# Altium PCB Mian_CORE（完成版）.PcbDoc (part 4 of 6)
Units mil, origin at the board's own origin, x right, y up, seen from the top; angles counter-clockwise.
Board outline 2755.91 x 1771.65 mil, 4 copper layers (TOP, GND02, PWR03, BOTTOM); 61 components, 130 nets, 4907 pads, 497 vias.
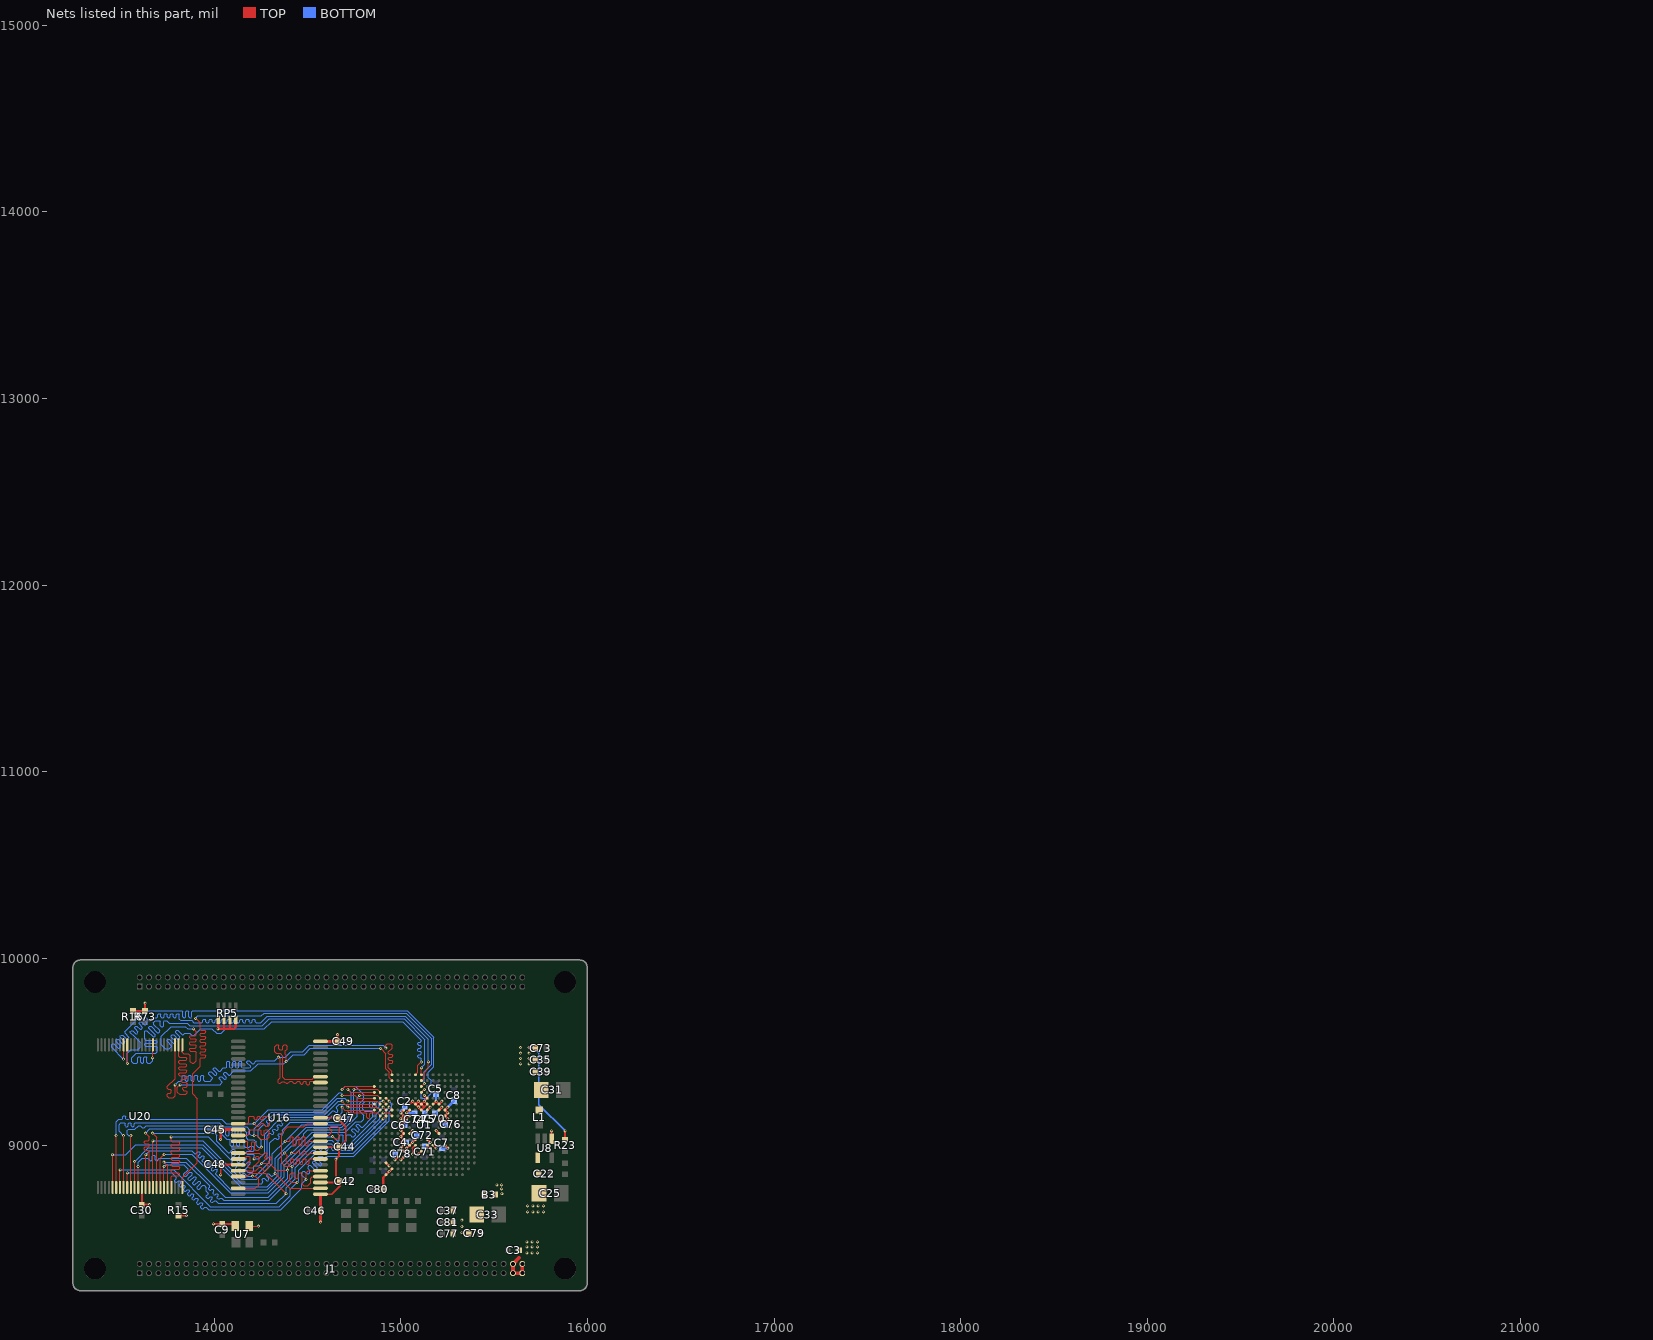
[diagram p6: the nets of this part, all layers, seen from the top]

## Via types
v1: diameter 16, hole 8, TOP to BOTTOM, tented both sides, 497 vias

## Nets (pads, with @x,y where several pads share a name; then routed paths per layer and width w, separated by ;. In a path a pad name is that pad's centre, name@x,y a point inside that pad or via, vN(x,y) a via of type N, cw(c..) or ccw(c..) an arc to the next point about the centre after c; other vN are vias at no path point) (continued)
A13: U1.R1 U16.20 U20.3 | length 2952.1
  TOP w5.5: v1(13790,9323) 13790.01,9264.01 13780,9254 13756,9254 13749,9261 13749,9272 13755,9278 13764,9278 13769,9283 13769,9294 13765,9298 13755,9298 13749,9304 13749,9314 13790.01,9355.01 U20.3@13790.01,9536.89 ; v1(14344,9471) 14353,9462 14353,9360 14344,9351 14344,9334 14348,9330 14354,9330 14364,9340 14376,9340 14386,9330 14395,9330 14407,9342 14415,9342 14425,9332 14437,9332 14447,9342 14456.3,9342 14461.25,9337.05 14461.25,9330.37 14466.2,9325.42 14472.8,9325.42 14477.75,9330.37 14477.75,9337.05 14482.7,9342 14489.3,9342 14494.25,9337.05 14494.25,9328.95 14499.2,9324 14505.8,9324 14510.75,9328.95 14510.75,9337.05 14515.7,9342 14530,9342 14539,9333 14567.5,9333 U16.20@14569.47,9334.98 ; v1(14920,9519) 14920,9536 14928,9544 14947,9544 14955,9536 14955,9520 14934,9499 14934,9491.7 14938.95,9486.75 14951.05,9486.75 14956,9481.8 14956,9475.2 14951.05,9470.25 14938.95,9470.25 14934,9465.3 14934,9458.7 14938.95,9453.75 14951.05,9453.75 14956,9448.8 14956,9442.2 14951.05,9437.25 14938.95,9437.25 14934,9432.3 14934,9413.77 14952.77,9395 U1.R1@14952.77,9376.72
  BOTTOM w5.5: v1(13790,9323) 13810,9343 13823.3,9343 13828.25,9347.95 13828.25,9369.05 13833.2,9374 13839.8,9374 13844.75,9369.05 13844.75,9347.95 13849.7,9343 13856.3,9343 13861.25,9347.95 13861.25,9369.05 13866.2,9374 13872.8,9374 13877.75,9369.05 13877.75,9347.95 13882.7,9343 13889.3,9343 13894.25,9347.95 13894.25,9369.05 13899.2,9374 13905.8,9374 13910.75,9369.05 13910.75,9347.95 13915.7,9343 13922.3,9343 13927.25,9347.95 13927.25,9369.05 13932.2,9374 13938.8,9374 13943.75,9369.05 13943.75,9347.95 13948.7,9343 13979,9343 13990.31,9354.31 13990.31,9361.31 13971.86,9379.77 13971.86,9386.77 13976.52,9391.43 13983.52,9391.43 14001.98,9372.98 14008.98,9372.98 14013.65,9377.65 14013.65,9384.65 13995.19,9403.1 13995.19,9410.1 13999.86,9414.77 14006.86,9414.77 14025.31,9396.31 14032.31,9396.31 14049,9413 14061.3,9413 14066.25,9417.95 14066.25,9444.05 14071.2,9449 14077.8,9449 14082.75,9444.05 14082.75,9417.95 14087.7,9413 14094.3,9413 14099.25,9417.95 14099.25,9444.05 14104.2,9449 14110.8,9449 14115.75,9444.05 14115.75,9417.95 14120.7,9413 14127.3,9413 14132.25,9417.95 14132.25,9444.05 14137.2,9449 14143.8,9449 14148.75,9444.05 14148.75,9417.95 14153.7,9413 14188,9413 14192,9417 14192,9424 14175.67,9440.33 14175.67,9447.33 14180.33,9452 14187.33,9452 14203.67,9435.67 14210.67,9435.67 14226,9451 14324,9451 v1(14344,9471) 14381,9471 14410,9500 14475,9500 14509,9534 14905,9534 v1(14920,9519)
A14: U1.R2 U16.21 U20.2 | length 2777.8
  TOP w5.5: U20.2@13809.69,9536.89 13809.69,9474.7 13814.64,9469.75 13848.74,9469.75 13853.69,9464.8 13853.69,9458.2 13848.74,9453.25 13814.64,9453.25 13809.69,9448.3 13809.69,9441.7 13814.64,9436.75 13848.74,9436.75 13853.69,9431.8 13853.69,9425.2 13848.74,9420.25 13814.64,9420.25 13809.69,9415.3 13809.69,9408.7 13814.64,9403.75 13848.74,9403.75 13853.69,9398.8 13853.69,9392.2 13848.74,9387.25 13814.64,9387.25 13809.69,9382.3 13809.69,9375.7 13814.64,9370.75 13848.74,9370.75 13853.69,9365.8 13853.69,9358.7 13848.74,9353.75 13828.64,9353.75 13823.69,9348.8 13823.69,9342.2 13828.64,9337.25 13846.75,9337.25 13856,9328 13856,9316 13851,9311 13836,9311 13831,9306 13831,9298 13837,9292 13851,9292 13856,9287 13856,9280 13847.5,9271.5 13814.5,9271.5 13803,9283 13803,9309 v1(13817,9323) ; v1(14385.45,9447.46) 14385.45,9483.55 14382,9487 14382,9504 14392,9514 14392,9529 14384,9537 14375,9537 14368,9530 14368,9513 14365,9510 14352,9510 14347,9515 14347,9532 14342,9537 14335,9537 14324,9526 14324,9500 14332,9492 14353,9492 14368,9477 14368,9364 14379,9353 14526,9353 14539.47,9366.47 U16.21@14569.47,9366.47 ; v1(14892,9518.45) 14920,9490.45 14920,9408.02 14937.02,9391 14937.02,9360.97 U1.R2@14952.77,9345.22
  BOTTOM w5.5: v1(13817,9323) 14032,9323 14041.76,9332.76 14041.76,9339.76 14027.54,9353.97 14027.54,9360.97 14032.21,9365.64 14039.21,9365.64 14053.42,9351.42 14060.42,9351.42 14065.09,9356.09 14065.09,9363.09 14050.88,9377.3 14050.88,9384.3 14055.54,9388.97 14062.54,9388.97 14076.76,9374.76 14083.76,9374.76 14106,9397 14197,9397 14236,9436 14373.98,9436 v1(14385.45,9447.46) 14422.98,9485 14482,9485 14515.45,9518.45 v1(14892,9518.45)
A15: U1.L1 U20.1 | length 2803.5
  TOP w5.5: U20.1@13829.38,9536.89 13829.38,9497.62 13837,9490 13862,9490 13873,9479 13873,9446 13882,9437 13890,9437 13904,9451 13904,9498.3 13899.05,9503.25 13872.95,9503.25 13868,9508.2 13868,9514.8 13872.95,9519.75 13899.05,9519.75 13904,9524.7 13904,9531.3 13899.05,9536.25 13872.95,9536.25 13868,9541.2 13868,9547.8 13872.95,9552.75 13899.05,9552.75 13904,9557.7 13904,9564.3 13899.05,9569.25 13872.95,9569.25 13868,9574.2 13868,9580.8 13872.95,9585.75 13899.05,9585.75 13904,9590.7 13904,9608 v1(13889,9623) ; U1.L1@15078.76,9376.72 15092,9389.96 15092,9427 v1(15110,9445)
  BOTTOM w5.5: v1(13889,9623) 13857,9623 13845,9635 13769,9635 13716,9582 13716,9537 13738,9515 13759,9515 13769.86,9525.86 13769.86,9532.86 13747.16,9555.56 13747.16,9562.56 13751.83,9567.23 13758.83,9567.23 13781.53,9544.53 13788.53,9544.53 13793.19,9549.19 13793.19,9556.2 13770.5,9578.89 13770.5,9585.89 13775.16,9590.56 13782.16,9590.56 13804.86,9567.86 13811.86,9567.86 13816.53,9572.53 13816.53,9579.53 13793.83,9602.23 13793.83,9609.23 13798.5,9613.9 13805.5,9613.9 13828.2,9591.2 13835.2,9591.2 13843,9599 13870,9599 13880,9589 13894,9589 13928,9623 13988,9623 14013,9598 14039,9598 14063,9622 14269,9622 14309,9662 15010,9662 15110,9562 15110,9555.7 15105.05,9550.75 15094.95,9550.75 15090,9545.8 15090,9539.2 15094.95,9534.25 15105.05,9534.25 15110,9529.3 15110,9522.7 15105.05,9517.75 15094.95,9517.75 15090,9512.8 15090,9506.2 15094.95,9501.25 15105.05,9501.25 15110,9496.3 15110,9489.7 15105.05,9484.75 15094.95,9484.75 15090,9479.8 15090,9473.2 15094.95,9468.25 15105.05,9468.25 15110,9463.3 v1(15110,9445)
A16: U1.K3 U20.48 | length 2830
  TOP w5.5: U20.48@13829.38,8773.11 13829.38,8824.38 13910,8905 13910,9248 13884,9274 13884,9381 13924,9421 13924,9462.3 13928.95,9467.25 13949.05,9467.25 13954,9472.2 13954,9478.8 13949.05,9483.75 13928.95,9483.75 13924,9488.7 13924,9495.3 13928.95,9500.25 13949.05,9500.25 13954,9505.2 13954,9511.8 13949.05,9516.75 13928.95,9516.75 13924,9521.7 13924,9528.3 13928.95,9533.25 13949.05,9533.25 13954,9538.2 13954,9544.8 13949.05,9549.75 13928.95,9549.75 13924,9554.7 13924,9561.3 13928.95,9566.25 13949.05,9566.25 13954,9571.2 13954,9577.8 13949.05,9582.75 13928.95,9582.75 13924,9587.7 13924,9594.3 13928.95,9599.25 13949.05,9599.25 13954,9604.2 13954,9610.8 13949.05,9615.75 13928.95,9615.75 13924,9620.7 13924,9655 v1(13900,9679) ; U1.K3@15110.25,9313.72 v1(15126,9329.47)
  BOTTOM w5.5: v1(13900,9679) 13913,9692 14253,9692 14267,9706 15029,9706 15165,9570 15165,9433 15126,9394 v1(15126,9329.47)
A17: U1.K4 U20.17 | length 2853.9
  TOP w5.5: v1(13514,9460) 13514.42,9460.42 U20.17@13514.42,9536.89 ; U1.K4@15110.25,9282.23 v1(15126,9297.98)
  BOTTOM w5.5: v1(13514,9460) 13451,9523 13451,9538 13455.33,9542.33 13462.33,9542.33 13485.03,9519.63 13492.03,9519.63 13496.7,9524.3 13496.7,9531.3 13474,9554 13474,9561 13478.66,9565.66 13485.66,9565.66 13508.36,9542.97 13515.36,9542.97 13520.03,9547.63 13520.03,9554.63 13497.33,9577.33 13497.33,9584.33 13502,9589 13509,9589 13531.7,9566.3 13538.7,9566.3 13543.36,9570.97 13543.36,9577.97 13520.67,9600.67 13520.67,9607.67 13633,9720 13826.3,9720 13831.25,9715.05 13831.25,9686.95 13836.2,9682 13842.8,9682 13847.75,9686.95 13847.75,9715.05 13852.7,9720 13859.3,9720 13864.25,9715.05 13864.25,9686.95 13869.2,9682 13875.8,9682 13880.75,9686.95 13880.75,9715.05 13885.7,9720 15034,9720 15176,9578 15176,9419.28 15147,9390.28 15147,9361.36 15162.36,9346 15162.36,9331 15148,9316.64 15148,9303.36 15162.36,9289 15162.36,9277.36 15136,9251 15114,9251 15110.25,9254.75 15110.25,9282.23 v1(15126,9297.98)
A18: U1.K2 U20.16 | length 2825
  TOP w5.5: U20.16@13534.1,9536.89 13534.1,9437.9 v1(13535,9437) ; U1.K2@15110.25,9345.22 15126,9360.97 15126,9388.28 15148,9410.28 v1(15148,9446)
  BOTTOM w5.5: v1(13535,9437) 13535,9493 13553,9511 13590,9511 13603,9524 13603,9550.03 13568.01,9585.01 13550.97,9602.05 13550.97,9609.05 13555.64,9613.72 13562.64,9613.72 13579.68,9596.68 13586.68,9596.68 13591.35,9601.35 13591.35,9608.35 13574.31,9625.39 13574.31,9632.39 13578.97,9637.06 13585.97,9637.06 13603.01,9620.01 13610.01,9620.01 13614.68,9624.68 13614.68,9631.68 13597.64,9648.72 13597.64,9655.72 13602.31,9660.39 13609.31,9660.39 13626.35,9643.35 13633.35,9643.35 13638.02,9648.02 13638.02,9655.02 13620.98,9672.06 13620.98,9679.06 13625.64,9683.73 13632.64,9683.73 13649.68,9666.68 13656.68,9666.68 13672,9682 13693.3,9682 13698.25,9686.95 13698.25,9699.05 13703.2,9704 13709.8,9704 13714.75,9699.05 13714.75,9686.95 13719.7,9682 13726.3,9682 13731.25,9686.95 13731.25,9699.05 13736.2,9704 13742.8,9704 13747.75,9699.05 13747.75,9686.95 13752.7,9682 13759.3,9682 13764.25,9686.95 13764.25,9699.05 13769.2,9704 13775.8,9704 13780.75,9699.05 13780.75,9686.95 13785.7,9682 13792.3,9682 13797.25,9686.95 13797.25,9699.05 13802.2,9704 13808.8,9704 13813.75,9699.05 13813.75,9674.25 13820,9668 13879,9668 13891,9656 13934.3,9656 13939.25,9660.95 13939.25,9669.05 13944.2,9674 13950.8,9674 13955.75,9669.05 13955.75,9660.95 13960.7,9656 13967.3,9656 13972.25,9660.95 13972.25,9669.05 13977.2,9674 13983.8,9674 13988.75,9669.05 13988.75,9660.95 13993.7,9656 14000.3,9656 14005.25,9660.95 14005.25,9669.05 14010.2,9674 14016.8,9674 14021.75,9669.05 14021.75,9660.95 14026.7,9656 14033.3,9656 14038.25,9660.95 14038.25,9669.05 14043.2,9674 14049.8,9674 14054.75,9669.05 14054.75,9660.95 14059.7,9656 14066.3,9656 14071.25,9660.95 14071.25,9669.05 14076.2,9674 14082.8,9674 14087.75,9669.05 14087.75,9660.95 14092.7,9656 14099.3,9656 14104.25,9660.95 14104.25,9669.05 14109.2,9674 14115.8,9674 14120.75,9669.05 14120.75,9660.95 14125.7,9656 14132.3,9656 14137.25,9660.95 14137.25,9669.05 14142.2,9674 14148.8,9674 14153.75,9669.05 14153.75,9660.95 14158.7,9656 14165.3,9656 14170.25,9660.95 14170.25,9669.05 14175.2,9674 14181.8,9674 14186.75,9669.05 14186.75,9660.95 14191.7,9656 14198.3,9656 14203.25,9660.95 14203.25,9669.05 14208.2,9674 14214.8,9674 14219.75,9669.05 14219.75,9660.95 14224.7,9656 14249,9656 14284,9691 15024,9691 15148,9567 v1(15148,9446)
A19: U1.K1 U20.9 | length 2837.7
  TOP w5.5: v1(13670,9467) 13670,9534.99 U20.9@13671.9,9536.89 ; U1.K1@15110.25,9376.72 v1(15110.25,9413.75)
  BOTTOM w5.5: v1(13670,9467) 13670,9452 13657,9439 13644.7,9439 13639.75,9443.95 13639.75,9468.05 13634.8,9473 13628.2,9473 13623.25,9468.05 13623.25,9443.95 13618.3,9439 13611.7,9439 13606.75,9443.95 13606.75,9468.05 13601.8,9473 13595.2,9473 13590.25,9468.05 13590.25,9443.95 13585.3,9439 13565,9439 13557,9447 13557,9468 13582,9493 13688,9493 13694.62,9499.62 13694.62,9524.8 13689.67,9529.75 13631.57,9529.75 13626.62,9534.7 13626.62,9541.3 13631.57,9546.25 13689.67,9546.25 13694.62,9551.2 13694.62,9557.8 13689.67,9562.75 13631.57,9562.75 13626.62,9567.7 13626.62,9608.62 13631.29,9613.29 13638.29,9613.29 13672.3,9579.28 13679.3,9579.28 13683.97,9583.94 13683.97,9590.94 13649.96,9624.96 13649.96,9631.96 13654.62,9636.62 13661.62,9636.62 13695.64,9602.61 13702.64,9602.61 13707.3,9607.28 13707.3,9614.28 13673.29,9648.29 13673.29,9655.29 13683,9665 13707.3,9665 13712.25,9660.05 13712.25,9639.95 13717.2,9635 13723.8,9635 13728.75,9639.95 13728.75,9660.05 13733.7,9665 13747,9665 13760,9652 13856,9652 13868,9640 14258,9640 14294.01,9676.01 15017.99,9676.01 15129,9565 15129,9432.5 v1(15110.25,9413.75)
D0: U1.U4 U16.2 U20.29 | length 2414.2
  TOP w5.5: v1(13455,8948) 13455.36,8947.64 U20.29@13455.36,8773.11 ; v1(14326,8847) 14404.95,8768.05 U16.2@14569.47,8768.05 U16.2@14571.52,8766 ; v1(14748.05,9297.98) 14874.03,9297.98 U1.U4@14889.78,9282.23
  BOTTOM w5.5: v1(13455,8948) 13526,8948 13580,9002 13938,9002 14147,8793 14255,8793 14261.31,8799.31 14261.31,8806.31 14257.01,8810.61 14257.01,8817.61 14261.68,8822.27 14268.68,8822.27 14281.48,8809.48 14288.48,8809.48 14293.14,8814.14 14293.14,8821.14 14280.34,8833.94 14280.34,8840.94 14285.01,8845.61 14292.01,8845.61 14304.81,8832.81 14311.81,8832.81 v1(14326,8847) 14326,8928 14493.2,9095.2 14684.2,9095.2 14748.05,9159.05 v1(14748.05,9297.98)
D1: U1.R7 U16.4 U20.31 | length 2329.8
  TOP w5.5: U20.31@13494.73,8773.11 13494.73,8865.73 v1(13496,8867) ; v1(14445,8800.09) 14413,8800.09 14405,8808.09 14405,8840 14416,8851 14426,8851 14430,8847 14430,8829 14436,8823 14447,8823 14450,8826 14450,8843 14458,8851 14467,8851 14472,8846 14472,8790 14480,8782 14502,8782 14517,8797 14517,8823 14525.04,8831.04 U16.4@14569.47,8831.04 ; v1(14937.02,9203.49) U1.R7@14952.77,9187.74
  BOTTOM w5.5: v1(13496,8867) 13782,8867 13979,8670 14349,8670 14408,8729 14408,8763.09 v1(14445,8800.09) 14453,8808.09 14453,8864 14545,8956 14744,8956 14921.28,9133.28 14921.28,9187.74 v1(14937.02,9203.49)
D2: U1.T5 U16.5 U20.33 | length 2558
  TOP w5.5: U20.33@13534.1,8773.11 13534.1,8850.1 v1(13535,8851) ; v1(14493,8816) 14493,8852.54 14503,8862.54 U16.5@14569.47,8862.54 ; U1.T5@14921.28,9250.73 v1(14937.02,9234.98)
  BOTTOM w5.5: v1(13535,8851) 13773,8851 13797.49,8826.51 13797.49,8819.51 13788.94,8810.95 13788.94,8803.95 13793.61,8799.28 13800.61,8799.28 13809.16,8807.84 13816.16,8807.84 13820.83,8803.17 13820.83,8796.17 13812.27,8787.61 13812.27,8780.61 13816.94,8775.95 13823.94,8775.95 13832.5,8784.5 13839.5,8784.5 13844.16,8779.84 13844.16,8772.84 13835.61,8764.28 13835.61,8757.28 13840.27,8752.61 13847.27,8752.61 13855.83,8761.17 13862.83,8761.17 13867.5,8756.5 13867.5,8749.5 13858.94,8740.95 13858.94,8733.95 13863.61,8729.28 13870.61,8729.28 13879.17,8737.83 13886.17,8737.83 13890.83,8733.17 13890.83,8726.17 13882.28,8717.61 13882.28,8710.61 13886.94,8705.94 13893.94,8705.94 13902.5,8714.5 13909.5,8714.5 13914.17,8709.83 13914.17,8702.83 13905.61,8694.28 13905.61,8687.28 13910.28,8682.61 13917.28,8682.61 13925.83,8691.17 13932.83,8691.17 13937.5,8686.5 13937.5,8679.5 13928.95,8670.94 13928.95,8663.94 13933.61,8659.27 13940.61,8659.27 13949.17,8667.83 13956.17,8667.83 13970,8654 14355.63,8654 14470,8768.37 14470,8793 v1(14493,8816) 14470,8839 14470,8851.99 14478.29,8860.28 14483.72,8860.28 14498,8846 14506,8846 14512,8852 14512,8863 14503,8872 14503,8885 14508.91,8890.9 14515.91,8890.9 14541.43,8865.37 14548.43,8865.37 14553.1,8870.04 14553.1,8877.04 14527.57,8902.56 14527.57,8909.57 14532.24,8914.23 14539.24,8914.23 14564.77,8888.71 14571.77,8888.71 14576.43,8893.37 14576.43,8900.37 14550.91,8925.9 14550.91,8932.9 14559.01,8941 14579,8941 14582.25,8937.75 14582.25,8919.95 14587.2,8915 14593.8,8915 14598.75,8919.95 14598.75,8936.05 14603.7,8941 14749,8941 14938.5,9130.5 14938.5,9178.73 14952.77,9193 14952.77,9219.24 v1(14937.02,9234.98)
D3: U1.U5 U16.7 U20.35 | length 2299.3
  TOP w5.5: U20.35@13573.47,8773.11 v1(13573.47,8911) ; v1(14377.36,8957.36) 14392,8942.72 14392,8934 14386,8928 14386,8909.73 14398.2,8897.53 14404.8,8897.53 14409.75,8902.48 14409.75,8920.58 14414.7,8925.53 14421.3,8925.53 14426.25,8920.58 14426.25,8902.48 14431.2,8897.53 14437.8,8897.53 14442.75,8902.48 14442.75,8920.58 14447.7,8925.53 14454.3,8925.53 14459.25,8920.58 14459.25,8902.48 14464.2,8897.53 14470.8,8897.53 14475.75,8902.48 14475.75,8920.58 14480.7,8925.53 14487.3,8925.53 14492.25,8920.58 14492.25,8902.48 14497.2,8897.53 14503.8,8897.53 14508.75,8902.48 14508.75,8920.58 14513.7,8925.53 U16.7@14569.47,8925.53 ; v1(14779.54,9266.48) 14874.03,9266.48 U1.U5@14889.78,9250.73
  BOTTOM w5.5: v1(13573.47,8911) 13647.47,8985 13933,8985 14141,8777 14283,8777 14343,8837 14343,8923 v1(14377.36,8957.36) 14416.73,8996.73 14426.73,8996.73 14443,9013 14443,9023 14451.5,9031.5 14460.5,9031.5 14480,9051 14480,9060 14501.6,9081.6 14692.6,9081.6 14766,9155 14766,9252.94 v1(14779.54,9266.48)
D4: U1.V3 U16.8 U20.38 | length 2492.6
  TOP w5.5: U20.38@13632.53,8773.11 13632.53,8946.53 v1(13634,8948) ; v1(14415,8957) 14438.3,8957.02 14443.25,8961.97 14443.25,8962.07 14448.2,8967.02 14454.8,8967.02 14459.75,8962.07 14459.75,8951.97 14464.7,8947.02 14471.3,8947.02 14476.25,8951.97 14476.25,8962.07 14481.2,8967.02 14487.8,8967.02 14492.75,8962.07 14492.75,8951.97 14497.7,8947.02 14504.3,8947.02 14509.25,8951.97 14509.25,8952.07 14514.2,8957.02 U16.8@14569.47,8957.02 ; v1(14685.5,9297) 14702.23,9313.72 U1.V3@14858.28,9313.72
  BOTTOM w5.5: v1(13634,8948) 13656,8970 13880,8970 13895.34,8954.66 13902.34,8954.67 13912.31,8964.64 13919.31,8964.64 13923.97,8959.97 13923.97,8952.97 13914,8943 13914,8936 13918.67,8931.33 13925.67,8931.33 13935.64,8941.3 13942.64,8941.3 13947.31,8936.63 13947.31,8929.63 13937.34,8919.66 13937.34,8912.66 13942,8908 13949,8908 13958.97,8917.97 13965.98,8917.97 13970.64,8913.3 13970.64,8906.3 13960.67,8896.33 13960.67,8889.33 13965.34,8884.66 13972.34,8884.66 13982.31,8894.63 13989.31,8894.63 13993.98,8889.96 13993.98,8882.96 13984.01,8872.99 13984.01,8865.99 13988.67,8861.33 13995.67,8861.33 14005.64,8871.3 14012.64,8871.3 14017.31,8866.63 14017.31,8859.63 14007.34,8849.66 14007.34,8842.66 14090,8760 14285,8760 14358,8833 14358,8900 v1(14415,8957) 14526,9068 14701,9068 14757.5,9124.5 14787.5,9124.5 14802,9139 14802,9159 14781,9180 14781,9225 14802,9246 14802,9269 14757,9314 14702.5,9314 v1(14685.5,9297)
D5: U1.V4 U16.10 U20.40 | length 2298
  TOP w5.5: U20.40@13671.9,8773.11 13672,8773.21 v1(13672,9022) ; v1(14380,9020.02) 14401.3,9020.02 14406.25,9024.97 14406.25,9039.07 14411.2,9044.02 14417.8,9044.02 14422.75,9039.07 14422.75,9000.97 14427.7,8996.02 14434.3,8996.02 14439.25,9000.97 14439.25,9039.07 14444.2,9044.02 14450.8,9044.02 14455.75,9039.07 14455.75,9000.97 14460.7,8996.02 14467.3,8996.02 14472.25,9000.97 14472.25,9039.07 14477.2,9044.02 14483.8,9044.02 14488.75,9039.07 14488.75,9000.97 14493.7,8996.02 14500.3,8996.02 14505.25,9000.97 14505.25,9015.07 14510.2,9020.02 U16.10@14569.47,9020.02 ; v1(14716.55,9297.98) 14732.3,9282.23 U1.V4@14858.28,9282.23
  BOTTOM w5.5: v1(13672,9022) 13940,9022 14146,8816 14229,8816 14312,8899 14312,8952.02 v1(14380,9020.02) 14468.78,9108.8 14677.8,9108.8 14735,9166 14735,9279.53 v1(14716.55,9297.98)
D6: U1.T6 U16.11 U20.42 | length 2452.9
  TOP w5.5: U20.42@13711.27,8773.11 13711.27,8929.27 v1(13732,8950) ; U16.11@14569.47,9051.51 14614.51,9051.51 14631,9068 14631,9077 14620,9088 14620,9096 14626,9102 14659,9102 14674,9087 14674,9076 14665,9067 14665,9057 14674,9048 14674,9042 14666,9034 14646,9034 v1(14635,9045) ; v1(14905.53,9234.98) U1.T6@14921.28,9219.24
  BOTTOM w5.5: v1(13732,8950) 13881,8950 14086,8745 14289,8745 14375,8831 14375,8892 14528,9045 v1(14635,9045) 14637,9045 14661,9021 14666,9021 14670,9025 14670,9049.25 14674.75,9054 14686.3,9054 14691.25,9049.05 14691.25,9016.95 14696.2,9012 14702.8,9012 14707.75,9016.95 14707.75,9049.05 14712.7,9054 14729,9054 14738,9045 14748,9045 14755.22,9052.22 14755.22,9059.22 14738.18,9076.27 14738.18,9083.27 14742.85,9087.93 14749.85,9087.93 14766.89,9070.89 14773.89,9070.89 14778.56,9075.56 14778.56,9082.56 14761.52,9099.6 14761.52,9106.6 14766.18,9111.27 14773.18,9111.27 14788.45,9096 14795,9096 14850,9151 14850,9175 14843,9182 14806,9182 14796,9192 14796,9221 14809.98,9234.98 14829.3,9234.98 14834.25,9230.03 14834.25,9203.93 14839.2,9198.98 14845.8,9198.98 14850.75,9203.93 14850.75,9230.03 14855.7,9234.98 14862.3,9234.98 14867.25,9230.03 14867.25,9203.93 14872.2,9198.98 14878.8,9198.98 14883.75,9203.93 14883.75,9230.03 14888.7,9234.98 v1(14905.53,9234.98)
D7: U1.R8 U16.13 U20.44 | length 2224.2
  TOP w5.5: v1(13730,8909) 13750.64,8888.36 U20.44@13750.64,8773.11 ; v1(14417.67,8885.67) 14381.33,8885.67 14361,8906 14361,9064 14394,9097 14480,9097 14497.5,9114.5 U16.13@14569.47,9114.5 ; v1(14905.53,9171.99) 14937.02,9171.99 U1.R8@14952.77,9156.24
  BOTTOM w5.5: v1(13730,8909) 13847,8909 13974.89,8781.11 13974.89,8774.11 13970.57,8769.8 13970.57,8762.8 13975.24,8758.13 13982.24,8758.13 13986.55,8762.45 13993.55,8762.45 13998.22,8757.78 13998.22,8750.78 13993.91,8746.47 13993.91,8739.47 13998.57,8734.8 14005.57,8734.8 14009.89,8739.11 14016.89,8739.11 14021.55,8734.45 14021.55,8727.45 14017.24,8723.13 14017.24,8716.13 14021.91,8711.46 14028.91,8711.46 14033.22,8715.78 14040.22,8715.78 14050.96,8705.04 14295.04,8705.04 14417.67,8827.67 v1(14417.67,8885.67) 14539,9007 14628,9007 14650,8985 14730,8985 14886,9141 14886,9152.46 v1(14905.53,9171.99)
D8: U1.V5 U16.42 U20.30 | length 2259.1
  TOP w5.5: v1(13475,9051) 13475,8773.16 U20.30@13475.05,8773.11 ; U16.42@14128.53,9114.5 14179.5,9114.5 14186,9121 14186,9148 14191,9153 14209.3,9153 14214.25,9148.05 14214.25,9139.95 14219.2,9135 14225.8,9135 14230.75,9139.95 14230.75,9148.05 14235.7,9153 14242.3,9153 14247.25,9148.05 14247.25,9139.95 14252.2,9135 14258.8,9135 14263.75,9139.95 14263.75,9148.05 14268.7,9153 14290,9153 14297,9146 14297,9108 14290,9101 14277,9101 14261,9117 14255,9117 14239,9101 14228.05,9101 v1(14214.54,9114.5) ; v1(14685.05,9266.48) 14752.52,9266.48 14768.27,9250.73 U1.V5@14858.28,9250.73
  BOTTOM w5.5: v1(13475,9051) 13475,9124 13488,9137 13505.3,9137 13510.25,9141.95 13510.25,9152.05 13515.2,9157 13521.8,9157 13526.75,9152.05 13526.75,9141.95 13531.7,9137 14041,9137 14063.5,9114.5 v1(14214.54,9114.5) 14290.44,9190.4 14578.4,9190.4 14669,9281 14681,9281 14685.05,9276.95 v1(14685.05,9266.48)
D9: U1.U6 U16.44 U20.32 | length 2336
  TOP w5.5: U20.32@13514.42,8773.11 13514.42,9049.42 13515,9050 v1@13516,9051 ; U16.44@14128.53,9051.51 14179.51,9051.51 14185,9057 14185,9076 14192,9083 14247.3,9083 14252.25,9078.05 14252.25,9057.95 14257.2,9053 14263.8,9053 14268.75,9057.95 14268.75,9078.05 14273.7,9083 14284,9083 14295,9072 14295,9043 14282,9030 14249,9030 14227.49,9051.51 v1(14214.54,9051.51) ; v1(14716.55,9234.98) 14726.98,9234.98 14785,9234.98 ; 14779.54,9234.98 14785,9234.98 ; U1.U6@14889.78,9219.24 14874.03,9234.98 14785,9234.98
  BOTTOM w5.5: v1(13514,9051) 13491,9074 13491,9110 13500,9119 13517.3,9119 13522.25,9114.05 13522.25,9103.95 13527.2,9099 13533.8,9099 13538.75,9103.95 13538.75,9114.05 13543.7,9119 13550.3,9119 13555.25,9114.05 13555.25,9103.95 13560.2,9099 13566.8,9099 13571.75,9103.95 13571.75,9114.05 13576.7,9119 14028,9119 14050,9097 14174,9097 14191,9080 14191,9058.51 14198,9051.51 v1(14214.54,9051.51) 14214.54,9086.54 14304.8,9176.8 14584.8,9176.8 14659,9251 14700.53,9251 v1(14716.55,9234.98)
D10: U1.V6 U16.45 U20.34 | length 2467.3
  TOP w5.5: 13554,8861 13554,8773.32 U20.34@13553.79,8773.11 13553.79,9050.79 v1(13554,9051) ; U16.45@14128.53,9020.02 14174.98,9020.02 14181,9014 14181,8979 14188,8972 14195.3,8972 14200.25,8976.95 14200.25,9013.05 14205.2,9018 14211.8,9018 14216.75,9013.05 14216.75,8976.95 14221.7,8972 14235.94,8972 v1(14253,8989.06) ; v1(14685.05,9234.98) 14700.8,9219.24 U1.V6@14858.28,9219.24
  BOTTOM w5.5: v1(13554,9051) 13542,9051 13535,9058 13535,9078 13541,9084 13575,9084 13595,9104 13603,9104 13615,9092 13624,9092 13636,9104 14023,9104 14048,9079 14058.3,9079 14063.25,9074.05 14063.25,9055.95 14068.2,9051 14074.8,9051 14079.75,9055.95 14079.75,9074.05 14084.7,9079 14091.3,9079 14096.25,9074.05 14096.25,9055.95 14101.2,9051 14107.8,9051 14112.75,9055.95 14112.75,9074.05 14117.7,9079 14124.3,9079 14129.25,9074.05 14129.25,9055.95 14134.2,9051 14140.8,9051 14145.75,9055.95 14145.75,9074.05 14150.7,9079 14162,9079 14174,9067 14174,9036 14181,9029 14213,9029 14225,9017 14225,8999.06 14235,8989.06 v1(14253,8989.06) 14253,9025 14235,9043 14235,9083 14261.87,9109.87 14268.87,9109.87 14277.42,9101.31 14284.42,9101.31 14289.09,9105.98 14289.09,9112.98 14280.53,9121.53 14280.53,9128.53 14285.2,9133.2 14292.2,9133.2 14300.76,9124.64 14307.76,9124.64 14312.42,9129.31 14312.42,9136.31 14303.87,9144.87 14303.87,9151.87 14315.2,9163.2 14592.2,9163.2 14663.98,9234.98 v1(14685.05,9234.98)
D11: U1.T7 U16.47 U20.36 | length 2290
  TOP w5.5: v1(13593,8885) 13593.16,8884.84 U20.36@13593.16,8773.11 ; U16.47@14128.53,8957.02 14240.98,8957.02 14250.91,8947.09 14257.91,8947.09 14270.71,8959.89 14277.71,8959.89 14282.38,8955.22 14282.38,8948.22 14269.58,8935.42 14269.58,8928.42 14274.24,8923.76 14281.24,8923.76 14294.04,8936.56 14301.04,8936.56 14305.71,8931.89 14305.71,8924.89 14292.91,8912.09 14292.91,8905.09 14333,8865 v1(14393,8865) ; v1(14905.53,9203.49) U1.T7@14921.28,9187.74
  BOTTOM w5.5: v1(13593,8885) 13593,8908 13615,8930 13647,8930 13651.25,8925.75 13651.25,8920.95 13656.2,8916 13662.8,8916 13667.75,8920.95 13667.75,8939.05 13672.7,8944 13679.3,8944 13684.25,8939.05 13684.25,8920.95 13689.2,8916 13695.8,8916 13700.75,8920.95 13700.75,8925.05 13705.7,8930 13849,8930 14059.82,8719.18 14289.18,8719.18 14393,8823 v1(14393,8865) 14393,8883 14537,9027 14631,9027 14659,8999 14722,8999 14868,9145 14868,9165.96 v1(14905.53,9203.49)
D12: U1.U7 U16.48 U20.39 | length 2463.7
  TOP w5.5: v1(13633,9064) 13652.21,9044.79 13652.21,9027.7 13647.26,9022.75 13631.16,9022.75 13626.21,9017.8 13626.21,9011.2 13631.16,9006.25 13647.26,9006.25 13652.21,9001.3 13652.21,8994.7 13647.26,8989.75 13631.16,8989.75 13626.21,8984.8 13626.21,8978.2 13631.16,8973.25 13647.26,8973.25 13652.21,8968.3 U20.39@13652.21,8773.11 ; U16.48@14128.53,8925.53 14159.53,8925.53 14175,8941 14188,8941 14192,8937 14192,8919 14182,8909 14182,8885 14188,8879 14207,8879 14241,8913 14241,8931 14233,8939 14228.02,8939 v1(14214.54,8925.53) ; v1(14716.55,9203.49) 14874.03,9203.49 U1.U7@14889.78,9187.74
  BOTTOM w5.5: v1(13633,9064) 13656,9087 14011,9087 14066,9032 14083,9032 14087.25,9027.75 14087.25,8998.95 14092.2,8994 14098.8,8994 14103.75,8998.95 14103.75,9027.05 14108.7,9032 14115.3,9032 14120.25,9027.05 14120.25,8998.95 14125.2,8994 14131.8,8994 14136.75,8998.95 14136.75,9027.05 14141.7,9032 14155,9032 14160,9027 14160,8993 14166,8987 14187,8987 14194,8994 14207,8994 14214.54,8986.46 14214.54,8971.7 14209.59,8966.75 14177.49,8966.75 14172.54,8961.8 14172.54,8955.2 14177.49,8950.25 14209.59,8950.25 14214.54,8945.3 v1(14214.54,8925.53) 14239.53,8925.53 14270,8956 14270,9059 14360.6,9149.6 14599.6,9149.6 14634.5,9184.5 14641.5,9184.5 14651.47,9174.52 14658.47,9174.52 14663.13,9179.19 14663.13,9186.19 14653.16,9196.16 14653.16,9203.16 14669,9219 14701.04,9219 v1(14716.55,9203.49)
D13: U1.V7 U16.50 U20.41 | length 2435.4
  TOP w5.5: v1(13670,9064) 13691.58,9042.42 U20.41@13691.58,8773.11 ; U16.50@14128.53,8862.54 14224,8862.54 14241.46,8880 14250.54,8880 14268,8862.54 14277.54,8862.54 14290,8875 14290,8888 14276,8902 v1(14254.01,8902) ; v1(14685.05,9203.49) 14700.8,9187.74 U1.V7@14858.28,9187.74
  BOTTOM w5.5: v1(13670,9064) 14002,9064 14014.5,9051.5 14014.5,9020.5 14075.24,8959.76 14082.24,8959.76 14100.7,8978.21 14107.7,8978.21 14112.37,8973.54 14112.37,8966.54 14093.91,8948.09 14093.91,8941.09 14098.58,8936.42 14105.58,8936.42 14124.03,8954.88 14131.03,8954.88 14135.7,8950.21 14135.7,8943.21 14117.25,8924.75 14117.25,8917.75 14126.33,8908.67 14133.33,8908.67 14158.86,8934.19 14165.86,8934.19 14170.53,8929.53 14170.53,8922.53 14145,8897 14145,8890 14149.67,8885.33 14156.67,8885.33 14182.19,8910.86 14189.2,8910.86 14193.86,8906.19 14193.86,8899.19 14168.34,8873.66 14168.34,8866.66 14180,8855 14204,8855 14211,8862 14211,8886 14215.28,8890.28 14242.29,8890.28 v1(14254.01,8902) 14283,8930.99 14283,9050 14296,9063 14301.66,9063 14308.06,9056.6 14315.06,9056.6 14319.72,9061.27 14319.72,9068.27 14314,9074 14314,9081 14318.66,9085.66 14325.66,9085.66 14331.39,9079.94 14338.39,9079.94 14343.06,9084.6 14343.06,9091.6 14337.33,9097.33 14337.33,9104.33 14342,9109 14349,9109 14354.73,9103.27 14361.73,9103.27 14366.39,9107.94 14366.39,9114.94 14360.67,9120.67 14360.67,9127.67 14369,9136 14613,9136 14633.37,9156.37 14666.37,9156.37 14685.05,9175.05 v1(14685.05,9203.49)
D14: U1.T8 U16.51 U20.43 | length 2356.9
  TOP w5.5: U20.43@13730.95,8773.11 13730.95,8884 v1@13730.95,8885.05 ; U16.51@14128.53,8831.04 14173,8831.04 14191.96,8850 14274,8850 v1(14385,8739) ; v1(14905.53,9140.5) U1.T8@14921.28,9156.24
  BOTTOM w5.5: v1@13730.95,8884 v1(13732,8884) 13742,8894 13836,8894 13857.78,8872.22 13857.78,8865.22 13837.91,8845.35 13837.91,8838.35 13842.58,8833.68 13849.58,8833.68 13869.45,8853.55 13876.45,8853.55 13881.12,8848.88 13881.12,8841.88 13861.25,8822.01 13861.25,8815.01 13865.91,8810.35 13872.92,8810.35 13892.78,8830.21 13899.79,8830.21 13904.45,8825.55 13904.45,8818.55 13884.58,8798.68 13884.58,8791.68 13889.25,8787.01 13896.25,8787.01 13916.12,8806.88 13923.12,8806.88 13927.79,8802.21 13927.79,8795.21 13907.92,8775.34 13907.92,8768.34 13912.58,8763.68 13919.58,8763.68 13939.45,8783.55 13946.45,8783.55 13958,8772 13958,8752 13967.09,8742.91 13967.09,8735.91 13958.53,8727.36 13958.53,8720.36 13963.2,8715.69 13970.2,8715.69 13978.76,8724.24 13985.76,8724.24 13990.42,8719.58 13990.42,8712.58 13981.87,8704.02 13981.87,8697.02 13986.53,8692.35 13993.53,8692.35 14002.09,8700.91 14009.09,8700.91 14023,8687 14333,8687 v1(14385,8739) 14385,8771 14434,8820 14434,8878 14528,8972 14541.3,8972 14546.25,8976.95 14546.25,8985.05 14551.2,8990 14557.8,8990 14562.75,8985.05 14562.75,8976.95 14567.7,8972 14574.3,8972 14579.25,8976.95 14579.25,8985.05 14584.2,8990 14590.8,8990 14595.75,8985.05 14595.75,8976.95 14600.7,8972 14607.3,8972 14612.25,8976.95 14612.25,8985.05 14617.2,8990 14623.8,8990 14628.75,8985.05 14628.75,8976.95 14633.7,8972 14737.03,8972 v1(14905.53,9140.5)
D15: U1.U8 U16.53 U20.45 | length 2545.5
  TOP w5.5: v1(13769,9044) 13770.32,9042.68 13770.32,9022.7 13775.27,9017.75 13811.37,9017.75 13816.32,9012.8 13816.32,9006.2 13811.37,9001.25 13775.27,9001.25 13770.32,8996.3 13770.32,8989.7 13775.27,8984.75 13811.37,8984.75 13816.32,8979.8 13816.32,8973.2 13811.37,8968.25 13775.27,8968.25 13770.32,8963.3 13770.32,8956.7 13775.27,8951.75 13811.37,8951.75 13816.32,8946.8 13816.32,8940.2 13811.37,8935.25 13775.27,8935.25 13770.32,8930.3 13770.32,8923.7 13775.27,8918.75 13811.37,8918.75 13816.32,8913.8 13816.32,8907.2 13811.37,8902.25 13775.27,8902.25 13770.32,8897.3 13770.32,8890.7 13775.27,8885.75 13811.37,8885.75 13816.32,8880.8 13816.32,8874.2 13811.37,8869.25 13775.27,8869.25 13770.32,8864.3 13770.32,8857.7 13775.27,8852.75 13811.37,8852.75 13816.32,8847.8 13816.32,8841.2 13811.37,8836.25 13775.27,8836.25 13770.32,8831.3 U20.45@13770.32,8773.11 ; U16.53@14153,8768.05 U16.53@14128.53,8768.05 14221.05,8768.05 14237.72,8784.72 14237.72,8817.28 14221,8834 v1(14206,8834) ; v1(14716.55,9171.99) 14813.3,9171.99 14818.25,9167.04 14818.25,9148.94 14823.2,9143.99 14829.8,9143.99 14834.75,9148.94 14834.75,9167.04 14839.7,9171.99 14874.03,9171.99 U1.U8@14889.78,9156.24
  BOTTOM w5.5: v1(13769,9044) 13967,9044 14097.05,8913.95 14097.05,8906.95 14091.32,8901.22 14091.32,8894.22 14095.99,8889.56 14102.99,8889.56 14108.72,8895.28 14115.72,8895.28 14120.38,8890.62 14120.38,8883.62 14114.66,8877.89 14114.66,8870.89 14119.32,8866.22 14126.32,8866.22 14132.05,8871.95 14139.05,8871.95 14143.72,8867.28 14143.72,8860.28 14137.99,8854.55 14137.99,8847.55 14142.66,8842.89 14149.66,8842.89 14155.39,8848.61 14162.39,8848.61 14177,8834 v1(14206,8834) 14221,8834 14298,8911 14298,9012 14323.29,9037.29 14330.29,9037.29 14336.02,9031.57 14343.02,9031.57 14347.69,9036.23 14347.69,9043.23 14341.96,9048.96 14341.96,9055.96 14346.63,9060.63 14353.63,9060.63 14359.36,9054.9 14366.36,9054.9 14371.02,9059.57 14371.02,9066.57 14365.3,9072.3 14365.3,9079.3 14408.4,9122.4 14666.96,9122.4 v1(14716.55,9171.99)
DP1V2: B3.1 C31.1 C35.2 C39.2 C70.1 C71.1 C72.1 C73.1 C74.1 C75.1 C76.1 L1.2 R23.1 U1.G7 U1.G9 U1.G11 U1.J7 U1.J12 U1.L12 U1.M7 U1.M11 U1.M13 U1.N14 | length 1130.5
  TOP w10: R23.1@15880,9027.84 v1(15880,9076)
  TOP w12: U1.N14@15015.76,8967.27 v1(15031.51,8983.02) U1.M13@15047.26,8998.76 v1(15063.01,9014.51) U1.L12@15078.76,9030.26 ; v1(15031.51,9171.99) U1.M7@15047.26,9187.74 ; U1.M11@15047.26,9061.76 v1(15063.01,9077.5) ; U1.J12@15141.75,9030.26 v1(15157.5,9014.51) ; U1.J7@15141.75,9187.74 v1(15157.5,9203.49) ; v1(15188.99,9077.5) U1.G11@15204.74,9061.76 ; U1.G9@15204.74,9124.75 v1(15220.49,9140.5) ; U1.G7@15204.74,9187.74 v1(15220.49,9203.49)
  BOTTOM w10: C75.1@15128,9169 15128,9173.99 v1(15157.5,9203.49) ; C70.1@15183,9170 15187,9170 v1(15220.49,9203.49) ; v1(15688,9522) 15712,9522 15739,9495 15739,9217 v1(15880,9076)
  BOTTOM w12: v1(15031.51,9171.99) 15071.01,9171.99 C74.1@15074,9169 ; v1(15063.01,9014.51) 15063.01,9030.01 C72.1@15085,9052 15085,9055.51 v1(15063.01,9077.5) ; C71.1@15128,8994 15136.98,8994 v1(15157.5,9014.51) ; v1(15220.49,9140.5) 15220.49,9128.51 C76.1@15238,9111
  other v1: 15541,8739 15540,8765 15515,8787 15540,8787 15642,9435 15688,9435 15642,9464 15688,9464 15642,9493 15688,9493 15642,9522
DP1V2_PLL: B3.2 C33.1 C37.2 C77.1 C78.1 C79.1 C80.1 C81.1 U1.K14 U1.L13 U1.N15 U1.P15 U1.R17 U1.T16 U1.T18 | length 305.4
  TOP w6: v1(15063.01,8951.52) 15063.01,8983.02
  TOP w10: C80.1@14905.53,8764.47 C80.1@14906,8764
  TOP w12: C80.1@14905.53,8764.47 14905.53,8825.54 U1.T18@14921.28,8841.28 v1(14937.02,8857.03) U1.R17@14952.77,8872.78 ; U1.T16@14921.28,8904.28 v1(14937.02,8888.53) ; v1(14968.52,8920.02) U1.P15@14984.27,8935.77 ; v1(15000.02,8920.02) U1.N15@15015.76,8935.77 ; 15063.01,8983.02 U1.L13@15078.76,8998.76 ; v1(15094.5,8951.52) U1.K14@15110.25,8967.27
  BOTTOM w12: v1(14968.52,8920.02) 14968.52,8950.52 C78.1@14971,8953
  other v1: 15327,8530 15327,8564 15327,8598
DP3V3: C2.1 C3.1 C4.1 C5.1 C6.1 C7.1 C8.1 C9.1 C22.2 C25.1 C30.1 C42.1 C44.1 C45.1 C46.1 C47.1 C48.1 C49.1 J1.81 J1.82 J1.83 J1.84 R15.1 R16.1 R73.1 RP5.5 RP5.6 RP5.7 RP5.8 U1.F7 U1.F8 U1.F9 U1.F13 U1.G6 U1.H6 U1.H13 U1.J5 U1.J6 U1.J13 U1.K6 U1.K7 U1.L6 U1.M6 U1.M8 U1.N7 U1.N8 U1.N9 U1.N10 U1.N11 U1.N12 U1.N13 U7.4 U8.1 U8.4 U16.1 U16.3 U16.9 U16.14 U16.27 U16.43 U16.49 U20.37 | length 3568
  TOP w10: R16.1@13564,9718.15 R73.1@13630,9718.15 v1(13630,9760) ; U20.37@13612.84,8773.11 13612.84,8681.84 C30.1@13612,8681 v1(13653.84,8681) ; R15.1@13809,8621.16 v1(13850.84,8621.16) ; v1(14034.92,8840.08) C48.1@14034.92,8896 14126.56,8896 U16.49@14128.53,8894.03 ; U16.3@14569.47,8799.54 14666.22,8799.54 C42.1@14673.68,8807 ; U16.9@14569.47,8988.52 14666,8988.52 C44.1@14666,8991 ; U16.14@14569.47,9146 14663,9146 C47.1@14666,9143 14666,9137 14705,9098 14705,9026.92 C44.1@14669.08,8991 14669.08,8942.08 v1(14652,8925) 14652,8828.68 C42.1@14673.68,8807 ; U16.1@14570,8736.02 U16.1@14569.47,8736.55 14630.55,8736.55 14673.68,8779.68 C42.1@14673.68,8807 ; U8.1@15808.4,9034.18 v1@15808.4,9075
  TOP w12: v1(13995,8577) C9.1@14043,8577 14101.81,8577 U7.4@14113.2,8565.61 ; RP5.5@14021.51,9670.13 14021.51,9624.51 v1(14020,9623) 14054,9623 ; RP5.6@14053.01,9670.13 14053.01,9623.99 14054,9623 ; RP5.7@14084.5,9670.13 14084.5,9623.5 14084,9623 ; RP5.8@14116,9670.13 14116,9633 14106,9623 14084,9623 ; v1(15000.02,8983.02) U1.N13@15015.76,8998.76 15000.02,9014.51 U1.N12@15015.76,9030.26 v1(15000.02,9046.01) U1.N11@15015.76,9061.76 v1(15000.02,9077.5) U1.N10@15015.76,9093.25 15000.02,9109 U1.N9@15015.76,9124.75 ; U1.N7@15015.76,9187.74 v1(15000.02,9171.99) U1.N8@15015.76,9156.24 ; U1.M8@15047.26,9156.24 v1(15031.51,9140.5) ; U1.M6@15047.26,9219.24 v1(15063.01,9234.98) U1.L6@15078.76,9219.24 ; 15126,9203.49 U1.K6@15110.25,9219.24 ; v1(15126,9266.48) U1.J5@15141.75,9250.73 v1(15126,9234.98) ; U1.J13@15141.75,8998.76 v1(15157.5,8983.02) ; U1.H13@15173.24,8998.76 v1(15188.99,8983.02) ; U1.H6@15173.24,9219.24 v1(15188.99,9234.98) U1.G6@15204.74,9219.24 v1(15220.49,9234.98) ; U1.F13@15236.24,8998.76 v1(15251.98,8983.02) ; U1.F9@15236.24,9124.75 v1(15251.98,9140.5) U1.F8@15236.24,9156.24 v1(15251.98,9171.99) U1.F7@15236.24,9187.74 v1(15251.98,9203.49) ; 14054,9623 14084,9623 ; U1.N9@15015.76,9124.75 v1(15031.51,9140.5) ; U1.N9@15015.76,9124.75 v1(15000.02,9140.5) U1.N8@15015.76,9156.24 ; U1.N8@15015.76,9156.24 v1(15031.51,9140.5) ; U1.L6@15078.76,9219.24 v1(15094.5,9234.98) U1.K6@15110.25,9219.24 ; U1.L6@15078.76,9219.24 v1(15094.5,9203.49) ; v1(15094.5,9203.49) U1.K6@15110.25,9219.24 ; v1(15094.5,9203.49) U1.K7@15110.25,9187.74 U1.J6@15141.75,9219.24 v1(15126,9234.98) ; U1.K6@15110.25,9219.24 v1(15126,9234.98)
  TOP w15: v1(14034.92,9030.92) C45.1@14034.92,9083 U16.43@14128.53,9083.01 ; U16.27@14569.47,9555.45 14569.92,9555 C49.1@14661.08,9555 v1(14661.08,9591.48) ; v1(14570,8587) C46.1@14570,8648 U16.1@14570,8736.02
  TOP w20: 15633.84,8396 J1.82@15600.95,8363.11 J1.81@15600.95,8313.11 J1.83@15650.95,8313.11 J1.84@15650.95,8363.11
  BOTTOM w12: v1(15000.02,8983.02) 15000.02,8985.02 C4.1@15030,9015 15000.02,9044.98 v1(15000.02,9046.01) ; v1(15000.02,9077.5) 15000.02,9086.09 C6.1@15019.92,9106 15031.51,9117.59 v1(15031.51,9140.5) ; v1(15000.02,9171.99) 15000.02,9184.02 C2.1@15021,9205 ; C5.1@15188,9271.16 15188.99,9270.17 v1(15188.99,9234.98) ; C7.1@15220.49,8983.02 v1(15251.98,8983.02) ; v1(15251.98,9203.49) 15252.49,9203.49 C8.1@15285,9236
  other v1: 15676,8422 15703.5,8422 15732,8422 15676,8454 15704,8454 15732,8454 15676,8481 15704,8481 15732,8481 15680,8642 15708,8642 15736,8642 15764,8642 15680,8674 15708,8674 15736,8674 15764,8674 15808.4,9076
EXT_RST: U7.3 | length 49.4
  TOP w5.5: U7.3@14188,8565.61 v1(14237.39,8565.61)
